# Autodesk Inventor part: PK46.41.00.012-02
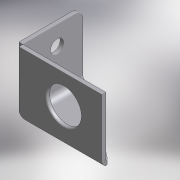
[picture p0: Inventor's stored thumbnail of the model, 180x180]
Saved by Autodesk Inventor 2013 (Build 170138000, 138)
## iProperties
Created: 2005-07
Part Number: PK46.41.00.012-02
Material: Steel, Mild
Document SubType Name: Листовой материал
Designer: tedescj
Manufacturer: Standard
Standards Organization: Custom
Density: 7.86 g/cm^3
Author: PVitaliy
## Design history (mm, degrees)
derived "PK46.41.00.012-01.ipt"
feature "Solid1::PK46.41.00.012-01.ipt" dims "d0" = 10
tag "TaggingFeature1"
body "Solid1"
other parameters: "Thickness" = 3.048, "BendRadius" = 3.048 (= Thickness), "BendReliefWidth" = 3.048 (= Thickness), "BendReliefDepth" = 1.524 (= 0.5 x Thickness), "CornerReliefSize" = 12.192 (= 4 x Thickness), "SeamGap" = 0.00508, "MinimumRemnant" = 6.096 (= 2 x Thickness), "TransitionRadius" = 3.048 (= BendRadius), "JacobiRadiusSize" = 3.048 (= BendRadius), "GapSize" = 3.048 (= Thickness)
